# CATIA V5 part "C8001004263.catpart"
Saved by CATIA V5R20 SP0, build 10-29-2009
Part number: C8001004263
Source: Unknown
Property "A": "50"
Property "ARTICLENO": "C8001004263"
Property "B": "23"
Property "BOMINFO": "C8001004263"
Property "C": "95"
Property "CA": "C8001004263"
Property "D1": "85"
Property "DES": "ROTATING EYEBOLT WITH RING Ton 10 M42x63"
Property "E": "95"
Property "H": "205"
Property "L": "63"
Property "LINA": "C8001004263"
Property "NB": "C8001004263"
Property "NBSYN": "$CODE."
Property "NN": "C800"
Property "NT": "Rotating eyebolt with ring"
Property "SIZE": "M42"
Property "SUPPLIER": "CF"
Property "SW": "75"
Property "WEIGHT": "10000"
Property "WLL": "10.00"
Bounding box of the stored display mesh (mm): x -47.825 to 48, y -63 to 227.825, z -42.5 to 42.5
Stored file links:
  C:\Users\Utente\Desktop\3D files 800\C8001004263.catpart
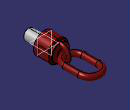
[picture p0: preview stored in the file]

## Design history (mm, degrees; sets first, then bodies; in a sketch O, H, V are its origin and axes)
Body1 "Geometry.1" (main body)
  Solid1 "C8001004263.catpart": solid without history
